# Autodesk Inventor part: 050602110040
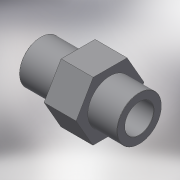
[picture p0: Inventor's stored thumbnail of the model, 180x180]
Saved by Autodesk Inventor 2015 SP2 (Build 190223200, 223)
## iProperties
Created: 2017-10
Part Number: 050602110040
Material: Generic
Description: PLASSON NIPPLE THR-CEM PVC 110(90)4"
Document SubType Name: Modeling
Designer: KIM
Mass: 537.16 g
Surface Area: 909.056 cm^2
Volume: 537.16 cm^3
Density: 1 g/cm^3
Appearance: Default
Author: KIM
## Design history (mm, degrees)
derived "050602.ipt"
feature "Solid1::050602.ipt"
tag "TaggingFeature1"
body "Solid1"
other parameters: "d0" = 122, "d13" = 0, "d14" = 0.9, "d17" = 61, "d18" = 49.2, "d21" = 113.03, "d22" = 51, "d23" = 85.5, "d24" = 81, "d25" = 41, "d26" = -61, "R_" = 113.03, "B_" = 12, "L_" = 61, "lt_" = 41, "H_" = 122, "l_" = 51
